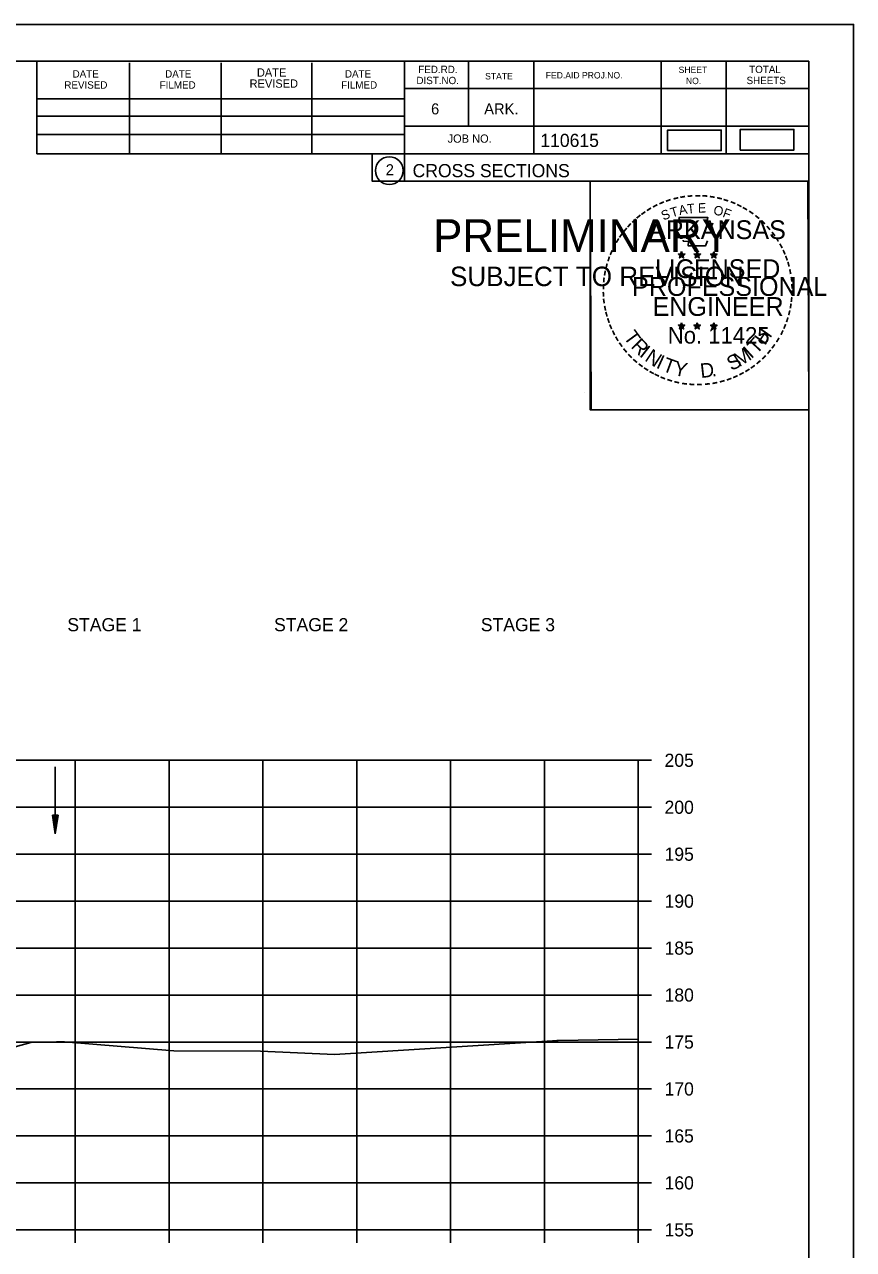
# Model space of a CAD drawing. Extents: x 1372132 to 1372465, y 380083 to 381790.
# Drawn here: x 1372376.6 to 1372464.9, y 381019.7 to 381150.2 of the extents above; entities that cross this region are included whole.
import ezdxf

# ---------------------------------------------------------------- set-up
doc = ezdxf.new("R2010")
doc.units = 0
for name, color, linetype in [('R_Axis', 7, 'Continuous'), ('R_Axis Annot', 7, 'Continuous'), ('R_Border', 7, 'Continuous'), ('R_Border PE', 7, 'Continuous'), ('R_Border Prem', 7, 'Continuous'), ('R_Dimension', 7, 'Continuous'), ('R_Draft', 7, 'Continuous'), ('R_Erosion', 7, 'Continuous'), ('R_Exist Surface', 7, 'Continuous'), ('R_Grid', 7, 'Continuous'), ('R_No Plot', 7, 'Continuous')]:
    doc.layers.add(name, color=color, linetype=linetype)

msp = doc.modelspace()

# ---------------------------------------------------------------- linework, layer by layer
at = {"layer": 'R_Axis'}
for p, q in [((1372442.01, 381021.83), (1372442.01, 381071.83)), ((1372443.41, 381071.83), (1372442.01, 381071.83)), ((1372443.41, 381066.83), (1372442.01, 381066.83)), ((1372443.41, 381061.83), (1372442.01, 381061.83)), ((1372443.41, 381056.83), (1372442.01, 381056.83)), ((1372443.41, 381051.83), (1372442.01, 381051.83)), ((1372443.41, 381046.83), (1372442.01, 381046.83)), ((1372443.41, 381041.83), (1372442.01, 381041.83)), ((1372443.41, 381036.83), (1372442.01, 381036.83)), ((1372443.41, 381031.83), (1372442.01, 381031.83)), ((1372443.41, 381026.83), (1372442.01, 381026.83)), ((1372162.01, 381021.83), (1372442.01, 381021.83)), ((1372382.01, 381020.43), (1372382.01, 381021.83)), ((1372392.01, 381020.43), (1372392.01, 381021.83)), ((1372402.01, 381020.43), (1372402.01, 381021.83)), ((1372412.01, 381020.43), (1372412.01, 381021.83)), ((1372422.01, 381020.43), (1372422.01, 381021.83)), ((1372432.01, 381020.43), (1372432.01, 381021.83)), ((1372442.01, 381020.43), (1372442.01, 381021.83)), ((1372443.41, 381021.83), (1372442.01, 381021.83))]:
    msp.add_line(p, q, dxfattribs=at)
at = {"layer": 'R_Border'}
for p, q in [((1372144.01, 381146.29), (1372460.19, 381146.29)), ((1372377.93, 381136.41), (1372377.93, 381146.29)), ((1372387.79, 381136.41), (1372387.79, 381146.09)), ((1372397.55, 381136.41), (1372397.55, 381146.09)), ((1372407.23, 381136.41), (1372407.23, 381146.09)), ((1372417.09, 381146.29), (1372417.09, 381133.49)), ((1372423.93, 381146.29), (1372423.93, 381139.35)), ((1372430.87, 381146.29), (1372430.87, 381136.41)), ((1372444.45, 381146.29), (1372444.45, 381136.41)), ((1372451.39, 381146.29), (1372451.39, 381136.41)), ((1372460.19, 380940.83), (1372460.19, 381146.29)), ((1372460.19, 381143.35), (1372417.09, 381143.35)), ((1372460.19, 381143.37), (1372460.19, 381143.37)), ((1372377.93, 381142.27), (1372417.09, 381142.27)), ((1372377.93, 381140.41), (1372417.09, 381140.41)), ((1372377.93, 381136.41), (1372377.93, 381138.47)), ((1372377.93, 381138.47), (1372417.09, 381138.47)), ((1372460.19, 381139.35), (1372417.09, 381139.35)), ((1372420.05, 381139.35), (1372460.19, 381139.35)), ((1372460.19, 381136.41), (1372377.93, 381136.41)), ((1372417.09, 381133.49), (1372460.19, 381133.49))]:
    msp.add_line(p, q, dxfattribs=at)
msp.add_circle((1372415.48, 381134.62), 1.47, dxfattribs=at)
at = {"layer": 'R_Border PE'}
for p, q in [((1372446.28, 381125.74), (1372446.63, 381125.63)), ((1372446.28, 381125.74), (1372446.53, 381125.7)), ((1372446.28, 381125.74), (1372446.52, 381125.62)), ((1372446.41, 381125.33), (1372446.63, 381125.63)), ((1372446.41, 381125.33), (1372446.54, 381125.58)), ((1372446.41, 381125.33), (1372446.63, 381125.55)), ((1372446.63, 381125.99), (1372446.59, 381125.74)), ((1372446.63, 381125.63), (1372446.63, 381125.99)), ((1372446.63, 381125.99), (1372446.68, 381125.74)), ((1372446.98, 381125.74), (1372446.63, 381125.63)), ((1372446.84, 381125.33), (1372446.63, 381125.63)), ((1372446.84, 381125.33), (1372446.63, 381125.55)), ((1372446.98, 381125.74), (1372446.69, 381125.69)), ((1372446.84, 381125.33), (1372446.7, 381125.62)), ((1372446.98, 381125.74), (1372446.77, 381125.64)), ((1372447.95, 381125.74), (1372448.3, 381125.63)), ((1372447.95, 381125.74), (1372448.2, 381125.7)), ((1372447.95, 381125.74), (1372448.19, 381125.62)), ((1372448.08, 381125.33), (1372448.3, 381125.63)), ((1372448.08, 381125.33), (1372448.21, 381125.58)), ((1372448.08, 381125.33), (1372448.3, 381125.55)), ((1372448.3, 381125.99), (1372448.26, 381125.74)), ((1372448.3, 381125.63), (1372448.3, 381125.99)), ((1372448.3, 381125.99), (1372448.35, 381125.74)), ((1372448.65, 381125.74), (1372448.3, 381125.63)), ((1372448.51, 381125.33), (1372448.3, 381125.63)), ((1372448.51, 381125.33), (1372448.3, 381125.55)), ((1372448.65, 381125.74), (1372448.36, 381125.69)), ((1372448.51, 381125.33), (1372448.37, 381125.62)), ((1372448.65, 381125.74), (1372448.44, 381125.64)), ((1372449.71, 381125.73), (1372450.06, 381125.62)), ((1372449.71, 381125.73), (1372449.97, 381125.68)), ((1372449.71, 381125.73), (1372449.95, 381125.61)), ((1372449.85, 381125.32), (1372450.06, 381125.62)), ((1372449.85, 381125.32), (1372449.97, 381125.56)), ((1372449.85, 381125.32), (1372450.06, 381125.54)), ((1372450.06, 381125.98), (1372450.02, 381125.73)), ((1372450.06, 381125.62), (1372450.06, 381125.98)), ((1372450.06, 381125.98), (1372450.11, 381125.73)), ((1372450.41, 381125.73), (1372450.06, 381125.62)), ((1372450.28, 381125.32), (1372450.06, 381125.62)), ((1372450.28, 381125.32), (1372450.06, 381125.53)), ((1372450.41, 381125.73), (1372450.12, 381125.68)), ((1372450.28, 381125.32), (1372450.14, 381125.61)), ((1372450.41, 381125.73), (1372450.21, 381125.63)), ((1372446.28, 381118.17), (1372446.62, 381118.06)), ((1372446.28, 381118.17), (1372446.53, 381118.12)), ((1372446.28, 381118.17), (1372446.51, 381118.05)), ((1372446.41, 381117.76), (1372446.62, 381118.06)), ((1372446.41, 381117.76), (1372446.53, 381118)), ((1372446.41, 381117.76), (1372446.62, 381117.98)), ((1372446.62, 381118.42), (1372446.58, 381118.17)), ((1372446.62, 381118.06), (1372446.62, 381118.42)), ((1372446.62, 381118.42), (1372446.67, 381118.17)), ((1372446.97, 381118.17), (1372446.62, 381118.06)), ((1372446.84, 381117.76), (1372446.62, 381118.06)), ((1372446.84, 381117.76), (1372446.62, 381117.97)), ((1372446.97, 381118.17), (1372446.69, 381118.12)), ((1372446.84, 381117.76), (1372446.7, 381118.05)), ((1372446.97, 381118.17), (1372446.77, 381118.07)), ((1372447.94, 381118.17), (1372448.29, 381118.06)), ((1372447.94, 381118.17), (1372448.2, 381118.12)), ((1372447.94, 381118.17), (1372448.18, 381118.05)), ((1372448.08, 381117.76), (1372448.29, 381118.06)), ((1372448.08, 381117.76), (1372448.2, 381118)), ((1372448.08, 381117.76), (1372448.29, 381117.98)), ((1372448.29, 381118.42), (1372448.25, 381118.17)), ((1372448.29, 381118.06), (1372448.29, 381118.42)), ((1372448.29, 381118.42), (1372448.34, 381118.17)), ((1372448.64, 381118.17), (1372448.29, 381118.06)), ((1372448.51, 381117.76), (1372448.29, 381118.06)), ((1372448.51, 381117.76), (1372448.29, 381117.97)), ((1372448.64, 381118.17), (1372448.35, 381118.12)), ((1372448.51, 381117.76), (1372448.37, 381118.05)), ((1372448.64, 381118.17), (1372448.44, 381118.07)), ((1372449.71, 381118.16), (1372450.06, 381118.05)), ((1372449.71, 381118.16), (1372449.96, 381118.11)), ((1372449.71, 381118.16), (1372449.95, 381118.04)), ((1372449.84, 381117.75), (1372450.06, 381118.05)), ((1372449.84, 381117.75), (1372449.97, 381117.99)), ((1372449.84, 381117.75), (1372450.06, 381117.97)), ((1372450.06, 381118.41), (1372450.02, 381118.16)), ((1372450.06, 381118.05), (1372450.06, 381118.41)), ((1372450.06, 381118.41), (1372450.11, 381118.16)), ((1372450.41, 381118.16), (1372450.06, 381118.05)), ((1372450.27, 381117.75), (1372450.06, 381118.05)), ((1372450.27, 381117.75), (1372450.06, 381117.96)), ((1372450.41, 381118.16), (1372450.12, 381118.11)), ((1372450.27, 381117.75), (1372450.14, 381118.04)), ((1372450.41, 381118.16), (1372450.2, 381118.06))]:
    msp.add_line(p, q, dxfattribs=at)
for points in [[(1372446.32, 381129.62), (1372446.59, 381128.79)], [(1372449.83, 381128.7), (1372449.97, 381128.98), (1372449.29, 381128.96), (1372449.44, 381129.62), (1372446.32, 381129.62)], [(1372446.81, 381127.2), (1372446.81, 381127.11), (1372447.38, 381127.09), (1372447.32, 381126.62), (1372449.19, 381126.62), (1372449.39, 381127.15)], [(1372446.63, 381125.99), (1372446.84, 381125.33), (1372446.28, 381125.74), (1372446.98, 381125.74), (1372446.41, 381125.33), (1372446.63, 381125.99)], [(1372448.3, 381125.99), (1372448.51, 381125.33), (1372447.95, 381125.74), (1372448.65, 381125.74), (1372448.08, 381125.33), (1372448.3, 381125.99)], [(1372450.06, 381125.98), (1372450.28, 381125.32), (1372449.71, 381125.73), (1372450.41, 381125.73), (1372449.85, 381125.32), (1372450.06, 381125.98)], [(1372446.62, 381118.42), (1372446.84, 381117.76), (1372446.28, 381118.17), (1372446.97, 381118.17), (1372446.41, 381117.76), (1372446.62, 381118.42)], [(1372448.29, 381118.42), (1372448.51, 381117.76), (1372447.94, 381118.17), (1372448.64, 381118.17), (1372448.08, 381117.76), (1372448.29, 381118.42)], [(1372450.06, 381118.41), (1372450.27, 381117.75), (1372449.71, 381118.16), (1372450.41, 381118.16), (1372449.84, 381117.75), (1372450.06, 381118.41)]]:
    msp.add_lwpolyline(points, dxfattribs=at)
for centre, radius in [((1372446.63, 381125.63), 0.172), ((1372446.63, 381125.63), 0.145), ((1372446.63, 381125.63), 0.116), ((1372446.63, 381125.63), 0.0991), ((1372446.63, 381125.63), 0.0747), ((1372446.63, 381125.63), 0.0495), ((1372446.63, 381125.63), 0.0296), ((1372448.3, 381125.63), 0.172), ((1372448.3, 381125.63), 0.145), ((1372448.3, 381125.63), 0.116), ((1372448.3, 381125.63), 0.0991), ((1372448.3, 381125.63), 0.0747), ((1372448.3, 381125.63), 0.0495), ((1372448.3, 381125.63), 0.0296), ((1372450.06, 381125.62), 0.172), ((1372450.06, 381125.62), 0.145), ((1372450.06, 381125.62), 0.116), ((1372450.06, 381125.62), 0.0991), ((1372450.06, 381125.62), 0.0747), ((1372450.06, 381125.62), 0.0495), ((1372450.06, 381125.62), 0.0296), ((1372446.62, 381118.06), 0.172), ((1372446.62, 381118.06), 0.145), ((1372446.62, 381118.06), 0.116), ((1372446.62, 381118.06), 0.0991), ((1372446.62, 381118.06), 0.0747), ((1372446.62, 381118.06), 0.0495), ((1372446.62, 381118.06), 0.0296), ((1372448.29, 381118.06), 0.172), ((1372448.29, 381118.06), 0.145), ((1372448.29, 381118.06), 0.116), ((1372448.29, 381118.06), 0.0991), ((1372448.29, 381118.06), 0.0747), ((1372448.29, 381118.06), 0.0495), ((1372448.29, 381118.06), 0.0296), ((1372450.06, 381118.05), 0.172), ((1372450.06, 381118.05), 0.145), ((1372450.06, 381118.05), 0.116), ((1372450.06, 381118.05), 0.0991), ((1372450.06, 381118.05), 0.0747), ((1372450.06, 381118.05), 0.0495), ((1372450.06, 381118.05), 0.0296)]:
    msp.add_circle(centre, radius, dxfattribs=at)
at = {"layer": 'R_Dimension'}
for p, q in [((1372379.58, 381065.99), (1372379.88, 381063.99)), ((1372380.18, 381065.99), (1372379.58, 381065.99)), ((1372379.58, 381065.99), (1372379.88, 381063.99)), ((1372380.18, 381065.99), (1372379.58, 381065.99)), ((1372379.63, 381065.99), (1372379.88, 381064.32)), ((1372379.63, 381065.99), (1372379.88, 381064.32)), ((1372379.68, 381065.99), (1372379.88, 381064.67)), ((1372379.68, 381065.99), (1372379.88, 381064.67)), ((1372379.73, 381065.99), (1372379.88, 381065)), ((1372379.73, 381065.99), (1372379.88, 381065)), ((1372379.79, 381065.99), (1372379.88, 381065.34)), ((1372379.79, 381065.99), (1372379.88, 381065.34)), ((1372379.84, 381065.99), (1372379.88, 381065.67)), ((1372379.84, 381065.99), (1372379.88, 381065.67)), ((1372380.18, 381065.99), (1372379.88, 381063.99)), ((1372379.98, 381065.99), (1372379.88, 381065.34)), ((1372380.08, 381065.99), (1372379.88, 381064.67)), ((1372380.13, 381065.99), (1372379.88, 381064.32)), ((1372380.03, 381065.99), (1372379.88, 381065)), ((1372379.93, 381065.99), (1372379.88, 381065.67)), ((1372380.18, 381065.99), (1372379.88, 381063.99)), ((1372379.98, 381065.99), (1372379.88, 381065.34)), ((1372380.08, 381065.99), (1372379.88, 381064.67)), ((1372380.13, 381065.99), (1372379.88, 381064.32)), ((1372380.03, 381065.99), (1372379.88, 381065)), ((1372379.93, 381065.99), (1372379.88, 381065.67))]:
    msp.add_line(p, q, dxfattribs=at)
at = {"layer": 'R_Draft'}
msp.add_line((1372379.88, 381071.13), (1372379.88, 381063.99), dxfattribs=at)
at = {"layer": 'R_Erosion'}
for points in [[(1372445.13, 381136.75), (1372450.85, 381136.75), (1372450.85, 381138.94), (1372445.13, 381138.94)], [(1372452.88, 381136.81), (1372458.59, 381136.81), (1372458.59, 381139), (1372452.88, 381139)]]:
    msp.add_lwpolyline(points, close=True, dxfattribs=at)
at = {"layer": 'R_Exist Surface'}
msp.add_lwpolyline([(1372372.5, 381040.48), (1372377.27, 381041.77), (1372380, 381041.85), (1372380.85, 381041.84), (1372392.51, 381040.88), (1372401.77, 381040.86), (1372409.65, 381040.49), (1372432.87, 381041.96), (1372433.33, 381041.99), (1372433.46, 381042), (1372442.01, 381042.13)], dxfattribs=at)
at = {"layer": 'R_Grid'}
for p, q in [((1372162.01, 381071.83), (1372442.01, 381071.83)), ((1372382.01, 381021.83), (1372382.01, 381071.83)), ((1372392.01, 381021.83), (1372392.01, 381071.83)), ((1372402.01, 381021.83), (1372402.01, 381071.83)), ((1372412.01, 381021.83), (1372412.01, 381071.83)), ((1372422.01, 381021.83), (1372422.01, 381071.83)), ((1372432.01, 381021.83), (1372432.01, 381071.83)), ((1372442.01, 381021.83), (1372442.01, 381071.83)), ((1372162.01, 381066.83), (1372442.01, 381066.83)), ((1372162.01, 381061.83), (1372442.01, 381061.83)), ((1372162.01, 381056.83), (1372442.01, 381056.83)), ((1372162.01, 381051.83), (1372442.01, 381051.83)), ((1372162.01, 381046.83), (1372442.01, 381046.83)), ((1372162.01, 381041.83), (1372442.01, 381041.83)), ((1372162.01, 381036.83), (1372442.01, 381036.83)), ((1372162.01, 381031.83), (1372442.01, 381031.83)), ((1372162.01, 381026.83), (1372442.01, 381026.83)), ((1372162.01, 381021.83), (1372442.01, 381021.83))]:
    msp.add_line(p, q, dxfattribs=at)
at = {"layer": 'R_No Plot'}
for p, q in [((1372131.61, 381150.18), (1372464.95, 381150.18)), ((1372436.23, 381111.03), (1372436.23, 381111.03))]:
    msp.add_line(p, q, dxfattribs=at)
for points in [[(1372131.61, 381150.18), (1372464.95, 381150.18), (1372464.95, 380936.84), (1372131.61, 380936.84)], [(1372377.93, 381146.29), (1372377.93, 381136.41), (1372413.67, 381136.41), (1372413.67, 381133.49), (1372436.87, 381133.49), (1372436.87, 381109.15), (1372460.19, 381109.15), (1372460.19, 380940.83), (1372144.01, 380940.83), (1372144.01, 381146.29)], [(1372436.87, 381133.49), (1372460.07, 381133.49), (1372460.19, 381109.15), (1372436.99, 381109.15)]]:
    msp.add_lwpolyline(points, close=True, dxfattribs=at)

# ---------------------------------------------------------------- texts
at = {"layer": 'R_Axis Annot'}
for s, p in [('STAGE 1', (1372381.17, 381085.57)), ('STAGE 2', (1372403.2, 381085.57)), ('STAGE 3', (1372425.23, 381085.57)), ('205', (1372444.81, 381071.13)), ('200', (1372444.81, 381066.13)), ('195', (1372444.81, 381061.13)), ('190', (1372444.81, 381056.13)), ('185', (1372444.81, 381051.13)), ('180', (1372444.81, 381046.13)), ('175', (1372444.81, 381041.13)), ('170', (1372444.81, 381036.13)), ('165', (1372444.81, 381031.13)), ('160', (1372444.81, 381026.13)), ('155', (1372444.81, 381021.13))]:
    msp.add_text(s, height=1.4, dxfattribs=at).set_placement(p)
at = {"layer": 'R_Border'}
for s, height, p in [('DATE', 0.782, (1372381.73, 381144.53)), ('DATE', 0.782, (1372391.59, 381144.53)), ('DATE', 0.879, (1372401.37, 381144.63)), ('DATE', 0.782, (1372410.75, 381144.53)), ('FED.RD.', 0.782, (1372418.57, 381145.01)), ('STATE', 0.684, (1372425.69, 381144.33)), ('FED.AID PROJ.NO.', 0.684, (1372432.15, 381144.43)), ('SHEET', 0.684, (1372446.31, 381145.01)), ('TOTAL', 0.782, (1372453.83, 381145.01)), ('REVISED', 0.782, (1372380.85, 381143.35)), ('FILMED', 0.782, (1372391.01, 381143.35)), ('REVISED', 0.879, (1372400.59, 381143.45)), ('FILMED', 0.782, (1372410.35, 381143.35)), ('DIST.NO.', 0.782, (1372418.37, 381143.83)), ('NO.', 0.684, (1372447.09, 381143.83)), ('SHEETS', 0.782, (1372453.55, 381143.83)), ('6', 1.17, (1372419.93, 381140.61)), ('ARK.', 1.172, (1372425.59, 381140.61)), ('JOB NO.', 0.879, (1372421.69, 381137.59)), ('110615', 1.4, (1372431.57, 381137.14)), ('2', 1.17, (1372415.1, 381134.13)), ('CROSS SECTIONS', 1.4, (1372417.96, 381133.92))]:
    msp.add_text(s, height=height, rotation=360, dxfattribs=at).set_placement(p)
at = {"layer": 'R_Border PE'}
for s, height, rotation, p in [('-', 1.6, 10.2193, (1372446.5, 381131.15)), ('-', 1.6, 5.8968, (1372447.23, 381131.26)), ('-', 1.6, 0.1862, (1372448, 381131.33)), ('-', 1.6, 357.743, (1372448.72, 381131.32)), ('-', 1.6, 352.1617, (1372449.46, 381131.26)), ('-', 1.6, 34.0636, (1372443.2, 381129.79)), ('-', 1.6, 28.7918, (1372443.8, 381130.16)), ('-', 1.6, 24.3072, (1372444.43, 381130.48)), ('-', 1.6, 19.1761, (1372445.07, 381130.75)), ('T', 1, 16.4036, (1372445.59, 381129.63)), ('-', 1.6, 13.6301, (1372445.82, 381130.99)), ('A', 1, 11.2132, (1372446.42, 381129.88)), ('T', 1, 6.0228, (1372447.26, 381130.04)), ('E', 1, 0.8323, (1372448.37, 381130.15)), ('O', 1, 350.4515, (1372449.97, 381129.94)), ('-', 1.6, 347.2049, (1372450.18, 381131.15)), ('-', 1.6, 342.3362, (1372450.82, 381130.99)), ('-', 1.6, 337.8551, (1372451.55, 381130.77)), ('-', 1.6, 334.1211, (1372452.18, 381130.5)), ('-', 1.6, 329.6409, (1372452.76, 381130.22)), ('-', 1.6, 42.9622, (1372441.72, 381128.6)), ('-', 1.6, 38.9507, (1372442.15, 381129.02)), ('-', 1.6, 36.2317, (1372442.63, 381129.39)), ('ARKANSAS', 2, 360, (1372443.17, 381127.33)), ('S', 1, 21.594, (1372444.68, 381129.3)), ('F', 1, 340.0707, (1372450.93, 381129.72)), ('-', 1.6, 325.8627, (1372453.41, 381129.85)), ('-', 1.6, 320.5297, (1372454.02, 381129.43)), ('-', 1.6, 315.5786, (1372454.62, 381128.94)), ('-', 1.6, 50.6142, (1372440.87, 381127.64)), ('-', 1.6, 48.423, (1372441.27, 381128.12)), ('-', 1.6, 309.8797, (1372455.18, 381128.39)), ('-', 1.6, 306.6522, (1372455.71, 381127.79)), ('-', 1.6, 62.8713, (1372439.82, 381125.93)), ('-', 1.6, 58.0706, (1372440.13, 381126.54)), ('-', 1.6, 54.2325, (1372440.45, 381127.07)), ('-', 1.4, 303.6753, (1372456.2, 381127.22)), ('-', 1.6, 299.6684, (1372456.51, 381126.61)), ('-', 1.6, 72.3945, (1372439.34, 381124.69)), ('-', 1.6, 67.7743, (1372439.56, 381125.32)), ('DWB', 0.01, 360, (1372446.62, 381125.62)), ('DWB', 0.01, 360, (1372448.29, 381125.62)), ('DWB', 0.01, 360, (1372450.05, 381125.61)), ('-', 1.6, 294.6628, (1372456.84, 381126)), ('-', 1.6, 290.5728, (1372457.1, 381125.42)), ('-', 1.6, 75.461, (1372439.14, 381123.97)), ('LICENSED', 2, 360, (1372443.77, 381123.18)), ('-', 1.6, 285.1233, (1372457.33, 381124.84)), ('-', 1.6, 280.5493, (1372457.53, 381124.1)), ('-', 1.6, 85.1863, (1372438.93, 381122.57)), ('-', 1.6, 81.2013, (1372439.01, 381123.26)), ('PROFESSIONAL', 2, 360, (1372441.35, 381121.28)), ('-', 1.6, 276.5962, (1372457.69, 381123.33)), ('-', 1.6, 94.1959, (1372438.94, 381121.14)), ('-', 1.6, 89.0622, (1372438.91, 381121.87)), ('-', 1.6, 274.3301, (1372457.75, 381122.61)), ('-', 1.6, 269.9407, (1372457.79, 381121.98)), ('-', 1.6, 98.9479, (1372439.01, 381120.48)), ('-', 1.6, 101.7149, (1372439.15, 381119.74)), ('ENGINEER', 2, 360, (1372443.53, 381119.15)), ('-', 1.6, 260.9953, (1372457.7, 381120.66)), ('-', 1.6, 263.5172, (1372457.77, 381121.31)), ('-', 1.6, 105.4578, (1372439.31, 381119.15)), ('-', 1.6, 109.0874, (1372439.53, 381118.52)), ('-', 1.6, 252.8681, (1372457.4, 381119.26)), ('-', 1.6, 255.7626, (1372457.59, 381119.98)), ('-', 1.6, 114.0643, (1372439.78, 381117.92)), ('-', 1.6, 115.7289, (1372440.09, 381117.3)), ('T', 1.54, 306.0406, (1372440.38, 381116.89)), ('No. 11425', 1.757, 360, (1372445.16, 381116.2)), ('DWB', 0.01, 360, (1372446.61, 381118.05)), ('DWB', 0.01, 360, (1372448.28, 381118.05)), ('DWB', 0.01, 360, (1372450.05, 381118.04)), ('H', 1.54, 54.6088, (1372455.5, 381115.93)), ('-', 1.6, 244.6197, (1372456.92, 381117.96)), ('-', 1.6, 247.8887, (1372457.18, 381118.59)), ('-', 1.6, 120.4471, (1372440.44, 381116.72)), ('-', 1.6, 125.8934, (1372440.85, 381116.16)), ('R', 1.54, 314.005, (1372441.15, 381115.85)), ('T', 1.54, 46.6444, (1372454.61, 381114.99)), ('-', 1.6, 239.0712, (1372456.53, 381117.21)), ('-', 1.6, 130.7181, (1372441.31, 381115.6)), ('-', 1.6, 134.2238, (1372441.82, 381115.06)), ('I', 1.54, 321.9694, (1372442.05, 381114.91)), ('N', 1.54, 326.5002, (1372442.61, 381114.44)), ('S', 1.54, 26.9312, (1372451.93, 381113.26)), ('M', 1.54, 32.6563, (1372452.77, 381113.66)), ('I', 1.54, 42.1136, (1372454.05, 381114.51)), ('-', 1.6, 225.7653, (1372455.21, 381115.43)), ('-', 1.6, 231.2538, (1372455.69, 381115.99)), ('-', 1.6, 233.8452, (1372456.12, 381116.56)), ('-', 1.6, 138.9338, (1372442.35, 381114.59)), ('-', 1.6, 144.6463, (1372442.91, 381114.19)), ('-', 1.6, 148.0898, (1372443.47, 381113.82)), ('I', 1.54, 335.3603, (1372443.82, 381113.66)), ('T', 1.54, 339.8912, (1372444.48, 381113.33)), ('Y', 1.54, 347.8556, (1372445.7, 381112.88)), ('D', 1.54, 6.3969, (1372448.69, 381112.53)), ('-', 1.6, 215.7363, (1372454.14, 381114.44)), ('-', 1.6, 221.0851, (1372454.69, 381114.92)), ('-', 1.6, 151.5704, (1372444.05, 381113.49)), ('-', 1.6, 154.6002, (1372444.57, 381113.25)), ('-', 1.6, 158.5612, (1372445.19, 381112.99)), ('-', 1.6, 162.7983, (1372445.88, 381112.78)), ('.', 1.54, 13.7642, (1372449.88, 381112.65)), ('-', 1.6, 200.7184, (1372451.81, 381113.12)), ('-', 1.6, 204.2516, (1372452.43, 381113.39)), ('-', 1.6, 207.3568, (1372453.05, 381113.71)), ('-', 1.6, 212.2491, (1372453.61, 381114.06)), ('-', 1.6, 167.5555, (1372446.59, 381112.61)), ('-', 1.6, 173.1155, (1372447.37, 381112.5)), ('-', 1.6, 176.5183, (1372448.11, 381112.45)), ('-', 1.6, 181.5918, (1372448.86, 381112.47)), ('-', 1.6, 185.8167, (1372449.67, 381112.55)), ('-', 1.6, 191.2858, (1372450.4, 381112.68)), ('-', 1.6, 195.4743, (1372451.13, 381112.88))]:
    msp.add_text(s, height=height, rotation=rotation, dxfattribs=at).set_placement(p)
at = {"layer": 'R_Border Prem'}
for s, height, p in [('PRELIMINARY', 3.5, (1372420.15, 381125.95)), ('DWB', 0.01, (1372420.89, 381127.8)), ('SUBJECT TO REVISION', 2.0751, (1372421.95, 381122.32))]:
    msp.add_text(s, height=height, rotation=360, dxfattribs=at).set_placement(p)

doc.saveas('drawing.dxf')
